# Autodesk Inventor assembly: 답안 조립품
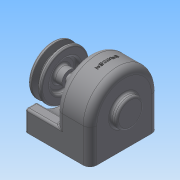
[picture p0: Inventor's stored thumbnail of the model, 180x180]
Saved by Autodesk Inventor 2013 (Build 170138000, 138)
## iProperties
Created: 2015-02
Part Number: 답안 조립품
Document SubType Name: Assembly
Designer: Administrator
Author: Administrator
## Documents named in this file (14)
- C:\Documents and Settings\Administrator\바탕 화면\450214V1018\답안 조립품.iam
- C:\Documents and Settings\Administrator\바탕 화면\450214V1018\1-본체.ipt
- C:\Documents and Settings\Administrator\바탕 화면\450214V1018\베어링 6001.ipt
- C:\Documents and Settings\Administrator\바탕 화면\450214V1018\축커버.ipt
- C:\Documents and Settings\Administrator\바탕 화면\450214V1018\축.ipt
- C:\Documents and Settings\Administrator\바탕 화면\450214V1018\오일실.ipt
- C:\Documents and Settings\Administrator\바탕 화면\450214V1018\키5x5.ipt
- C:\Documents and Settings\Administrator\바탕 화면\450214V1018\5-스퍼기어.ipt
- C:\Documents and Settings\Administrator\바탕 화면\450214V1018\M3x0.5.ipt
- C:\Documents and Settings\Administrator\바탕 화면\450214V1018\키4x4.ipt
- C:\Documents and Settings\Administrator\바탕 화면\450214V1018\4-V벨트풀리.ipt
- C:\Documents and Settings\Administrator\바탕 화면\450214V1018\M5x0.8.ipt
- M5x0.8.ipt
- C:\Documents and Settings\Administrator\바탕 화면\450214V1018\와샤.ipt
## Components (7 placed, 4 different names)
1. 1-본체:1
2. 4-V벨트풀리:1 — 플러쉬:1, 각도:4
3. M5x0.8:1
4. M3x0.5:1
5. M3x0.5:2
6. M3x0.5:3
7. M3x0.5:4
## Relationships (2: Flush 1, Angle 1)
- 플러쉬:1 [Flush]: 4-V벨트풀리:1
- 각도:4 [Angle]: 4-V벨트풀리:1
